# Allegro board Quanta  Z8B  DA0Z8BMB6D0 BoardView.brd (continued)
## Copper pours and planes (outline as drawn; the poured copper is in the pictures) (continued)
24737_DL on BOTTOM (solid shape): 160.58,189.63 160.58,187.98 160.51,187.9 159.77,187.9 159.77,189.63 159.9,189.76 160.46,189.76
51216_DRVH on BOTTOM (solid shape): 52.4,44.49 52.4,43.22 52.33,43.15 51.72,43.15 51.67,43.2 51.67,44.52 51.77,44.62 52.27,44.62
51216_DRVH on BOTTOM (solid shape): 55.99,34.74 55.99,34.51 55.88,34.41 55.58,34.41 55.48,34.51 54.94,34.51 54.76,34.33 54.76,31.95 54.74,31.92 54.59,31.92 54.56,31.95 54.56,34.74 54.94,35.12 55.6,35.12
51216_DRVL on BOTTOM (solid shape): 52.48,38.12 52.48,37.51 52.4,37.43 51.16,37.43 51,37.58 51,38.02 51.13,38.14 52.45,38.14
51216_DRVL on BOTTOM (solid shape): 53.55,32.71 53.55,31.9 53.54,31.9 52.61,31.9 52.27,32.23 52.27,32.68 52.33,32.73 53.52,32.73
51216_SW on BOTTOM (solid shape): 61.9,43.05 61.9,38.65 61.67,38.42 56.77,38.42 56.24,38.96 52.07,38.96 51.95,39.08 51.95,41.06 52.05,41.17 56.29,41.17 58.55,43.43 61.52,43.43
51216_SW on BOTTOM (solid shape): 56.39,35.48 56.39,35.2 56.24,35.04 55.88,35.04 55.58,35.35 54.79,35.35 54.36,34.92 54.36,31.95 54.33,31.92 54.18,31.92 54.15,31.95 54.15,35.4 54.41,35.65 56.21,35.65
51216_VBST on BOTTOM (solid shape): 56.04,34.11 56.04,33.34 55.91,33.22 55.4,33.22 55.17,32.99 55.17,31.95 55.15,31.92 54.99,31.92 54.97,31.94 54.97,33.75 55.37,34.16 55.99,34.16
51225_DH1 on TOP (solid shape): 43.59,61.92 43.59,61.66 43.41,61.49 42.47,61.49 42.45,61.46 42.45,61 42.42,60.98 42.27,60.98 42.22,61.03 42.22,61.79 42.39,61.97 43.03,61.97 43.16,62.1 43.41,62.1
51225_DH1 on BOTTOM (solid shape): 49.73,71.49 49.73,70.43 49.63,70.33 48.95,70.33 48.93,70.34 48.93,71.51 49.02,71.6 49.63,71.6
51225_DH2 on TOP (solid shape): 42.45,58.74 42.45,58.21 42.5,58.16 43.05,58.16 43.13,58.24 43.38,58.24 43.56,58.06 43.56,57.8 43.38,57.63 42.47,57.63 42.22,57.88 42.22,58.74 42.24,58.77 42.42,58.77
51225_DH2 on BOTTOM (solid shape): 48.82,47.01 48.82,45.87 48.77,45.81 48.01,45.81 47.93,45.89 47.93,47.06 47.96,47.08 48.74,47.08
51225_DL1 on TOP (solid shape): 44.38,60.98 44.38,60.72 44.2,60.55 42.67,60.55 42.65,60.57 42.65,60.75 42.67,60.78 43.72,60.78 43.77,60.83 43.77,60.98 43.94,61.16 44.2,61.16
51225_DL1 on BOTTOM (solid shape): 47.14,66.74 47.14,65.93 47.07,65.86 46.15,65.86 45.87,66.13 45.87,66.72 45.95,66.79 47.09,66.79
51225_DL2 on TOP (solid shape): 44.38,59 44.38,58.74 44.2,58.57 43.94,58.57 43.78,58.73 43.78,58.88 43.72,58.95 42.65,58.95 42.62,58.97 42.62,59.15 42.65,59.17 44.2,59.17
51225_DL2 on BOTTOM (solid shape): 49.97,54.2 49.97,53.71 49.81,53.56 47.68,53.56 47.65,53.59 47.65,54.4 47.73,54.48 49.69,54.48
51225_SW1 on TOP (solid shape): 42.55,63.98 42.55,63.72 42.37,63.54 41.84,63.54 41.63,63.34 41.63,61 41.61,60.98 41.45,60.98 41.43,61 41.43,63.47 42.11,64.15 42.37,64.15
51225_SW1 on BOTTOM (solid shape): 54.79,74.01 54.79,68.4 54.66,68.27 50.96,68.27 49.86,67.18 46.28,67.18 46.1,67.36 46.1,69.44 46.31,69.64 49.64,69.64 50.07,70.07 50.07,71.57 49.89,71.75 49,71.75 48.95,71.8 48.95,72.23 48.95,74.59 49.05,74.69 54.1,74.69
51225_SW2 on TOP (solid shape): 41.63,58.74 41.63,56.18 41.81,56 41.99,56 42.14,56.15 42.39,56.15 42.57,55.97 42.57,55.72 42.39,55.54 41.73,55.54 41.43,55.85 41.43,58.74 41.45,58.77 41.61,58.77
51225_SW2 on BOTTOM (solid shape): 53.14,52.57 53.14,46.88 52.99,46.73 50.4,46.73 49.86,47.26 48.01,47.26 47.93,47.34 47.93,49.98 47.58,50.34 45.65,50.34 45.09,50.89 45.09,52.8 45.26,52.98 52.73,52.98
51631_V5A on TOP (solid shape): 45.17,96.44 45.17,95.62 45.05,95.5 43.81,95.5 43.7,95.6 43.7,96.29 43.98,96.56 44.73,96.56 45.05,96.56
51631_V5A on BOTTOM (solid shape): 45.5,97.38 45.5,96.16 44.68,95.34 44.68,94.3 44.67,94.27 44.63,94.25 44.53,94.25 44.5,94.28 44.5,94.33 44.51,94.33 44.51,95.03 44.5,95.03 44.5,95.67 44.58,95.75 44.58,97.27 44.84,97.53 45.34,97.53
+AZA_VDD on TOP (solid shape): 33.29,25.92 33.29,25.17 33.68,24.79 33.68,23.94 33.66,23.92 33.64,23.92 33.12,23.92 32.71,24.33 32.71,24.55 32.5,24.76 32.5,25.07 32.1,25.48 32.1,26.42 32.13,26.46 32.76,26.46
+DDR_VTT_RUN on TOP (solid shape): 138.67,61.6 138.7,61.58 138.72,61.55 138.72,59.51 138.82,59.41 138.82,56.71 138.81,56.68 138.79,56.67 138.2,56 138.45,55.15 138.46,55.13 138.46,55.11 138.46,53.93 139.02,53.37 139.02,52.35 139.02,52.34 139.01,52.23 139.02,52.13 139.02,52.12 139.02,52 138.85,51.82 138.85,51.39 138.84,51.39 138.84,50.59 138.85,50.25 138.84,48.72 138.59,48.46 138.59,46.28 138.67,46.2 138.67,44.04 138.03,43.41 138.03,42.25 139.05,41.23 139.05,38.14 139.05,37.32 138.84,37.11 137.8,37.11 137.62,37.29 137.62,40.18 137.24,40.56 136.96,40.84 136.96,44.16 137.24,44.45 137.24,60.81 138.03,61.6
+DDR_VTT_RUN on BOTTOM (solid shape): 138.87,39.7 138.87,37.92 138.74,37.8 137.17,37.8 137.17,39.8 138.77,39.8
+DDR_VTT_RUN on BOTTOM (solid shape): 138.3,47.72 138.3,46.1 137.59,45.39 137.39,45.39 136.86,45.92 136.86,48.08 136.88,48.1 137.92,48.1
+DDR_VTT_RUN on BOTTOM (solid shape): 54.33,28.72 54.71,28.34 54.71,28.01 54.97,27.75 55.33,27.75 55.58,28.01 55.58,28.37 55.33,28.62 55.25,28.62 54.97,28.9 54.97,29.71 55.88,29.71 56.06,29.53 56.06,28.47 57.08,27.45 57.08,27.44 58.47,26.04 58.47,24.87 57.74,24.14 55.86,24.14 54.74,25.26 54.74,27.7 54.15,28.29 54.15,29.66 54.17,29.7 54.21,29.71 54.33,29.71
+DDR_VTT_RUN on BOTTOM (solid shape): 137.91,60.91 137.93,60.91 137.95,60.9 138.18,60.66 138.18,57.49 138.44,57.23 138.44,56.44 138.18,55.8 138.44,55.16 138.44,50.75 138.36,50.67 137.22,50.67 137.18,50.69 137.17,50.73 137.17,58.83 137.09,58.9 136.94,58.9 136.9,58.92 136.89,58.95 136.89,60.86 136.9,60.9 136.94,60.91
+DDR_VTT_RUN on IN1 (solid shape): 60.98,25.2 60.98,24.23 60.32,23.57 56.69,23.57 56.01,24.26 56.01,24.88 56.88,25.75 60.43,25.75
+DDR_VTT_RUN on IN1 (solid shape): 138.67,39.31 138.67,38.17 134.73,34.23 133.6,34.23 133,34.83 133,35.45 134.18,36.62 135.65,36.62 135.65,36.57 135.66,36.51 135.68,36.46 135.7,36.41 135.73,36.36 135.77,36.32 135.81,36.28 135.86,36.25 135.91,36.22 135.96,36.21 136.02,36.2 136.07,36.2 136.13,36.21 136.18,36.22 136.24,36.25 136.28,36.28 136.33,36.32 136.36,36.36 136.39,36.41 136.42,36.46 136.43,36.51 136.44,36.57 136.44,36.62 136.43,36.68 136.42,36.73 136.39,36.78 136.36,36.83 136.33,36.87 136.28,36.91 136.24,36.94 136.18,36.96 136.13,36.98 136.07,36.99 136.02,36.99 135.96,36.98 135.91,36.96 135.86,36.94 135.81,36.91 135.77,36.87 135.73,36.83 135.7,36.78 135.68,36.73 135.66,36.68 135.65,36.62 134.18,36.62 137.19,39.63 138.35,39.63
+FB_PLLAVDD on TOP (solid shape): 135.23,144.26 135.23,138.65 135.08,138.5 134.03,138.5 133.54,138.99 133.54,139.21 133.94,139.6 133.94,140.1 133.78,140.25 133.78,143.35 134.85,144.42 135.08,144.42
+FB_PLLAVDD on IN2 (solid shape): outline of 2246 points within 133.53,138.59 145.67,165.09
+G_SEN_PW on TOP (solid shape): 114.84,16.14 114.84,15.62 114.76,15.54 113.41,15.54 113.31,15.64 113.31,16.27 113.36,16.33 114.65,16.33
+G_SEN_PW on TOP (solid shape): 109.45,15.2 109.45,14.9 108.94,14.39 108.93,14.39 108.85,14.31 108.56,14.31 108.41,14.47 108.41,14.98 108.73,15.3 109.35,15.3
+G_SEN_PW on TOP (solid shape): 118.06,10.51 118.06,10.31 118.06,9.97 117.6,9.52 117.6,7.46 116.72,6.58 112.71,6.58 112.52,6.76 112.52,8.55 112.68,8.71 113.21,8.71 113.31,8.6 113.31,7.66 113.59,7.39 113.59,7.38 114.05,7.12 114.53,7.34 114.54,7.35 114.57,7.36 114.98,7.36 115,7.35 115.02,7.34 115.47,7.12 115.92,7.34 115.94,7.35 115.96,7.36 116.16,7.36 116.54,7.74 116.54,8.88 116.49,8.93 115.76,8.93 115.5,9.01 115.23,8.96 115.2,8.96 115.18,8.97 115.09,9.06 115.09,9.67 115.14,9.72 116.56,9.72 117.48,10.64 117.93,10.64
+G_SEN_PW on IN1 (solid shape): 118.93,14.86 118.93,11.52 117.98,10.57 117.98,10.26 117.76,10.04 117.54,10.04 117.4,10.18 117.4,10.96 118.3,11.87 118.3,14.51 117.24,15.57 109.88,15.57 108.95,14.64 108.95,14.39 108.79,14.23 108.53,14.23 108.37,14.39 108.37,15.17 109.36,16.17 109.36,16.18 117.6,16.18 117.6,16.18
+SM_VREF on TOP (solid shape): 94.81,76.76 94.81,76.02 94.81,75.98 95.03,75.76 95.68,75.76 95.94,75.51 95.94,74.01 95.55,73.62 95.55,73.01 95.54,72.95 95.53,72.89 95.53,72.84 95.53,70.92 95.55,70.91 95.55,67.29 94.26,66.01 93.58,66.01 93.25,66.34 93.25,70.96 93.5,71.21 93.5,74.42 93.5,74.82 93.88,75.2 93.88,76.68 94.14,76.93 94.64,76.93
+SM_VREF on TOP (solid shape): outline of 247 points within 97.61,80.39 99.7,84.78
+SMDDR_VREF_DIMM on TOP (solid shape): 95.01,38.33 95.01,36.36 95.02,36.35 95.02,34.76 94.8,34.54 93.5,34.54 93.32,34.71 93.32,36.35 92.95,36.73 92.95,38.71 93.07,38.83 94.52,38.83
+SMDDR_VREF_DIMM on TOP (solid shape): 114.6,52.7 114.6,50.72 114.6,50.71 114.6,49.25 114.52,49.17 114.49,49.16 114.46,49.16 114.31,49.18 114.15,49.13 114.12,49.12 114.09,49.14 113.96,49.27 113.96,50.38 113.64,50.71 113.64,52.57 113.84,52.78 114.51,52.78
+SMDDR_VREF_DIMM on TOP (solid shape): 113.43,40.53 113.57,40.51 113.71,40.53 114.46,40.53 115.24,39.74 115.24,38.8 115.2,38.76 115.16,38.75 115.14,38.76 114.74,38.87 114.36,38.7 112.75,38.7 112.73,38.73 112.73,39.97 113.29,40.53
+SMDDR_VREF_DIMM on BOTTOM (solid shape): 114.36,40.33 114.36,40.07 114.1,39.82 114.1,37.92 113.8,37.92 113.8,39.95 113.75,40.01 113.75,40.35 113.9,40.51 114.18,40.51
+SMDDR_VREF_DIMM on BOTTOM (solid shape): 114.13,50.69 114.58,50.23 114.58,49.44 114.55,49.36 114.46,49.34 114.3,49.36 114.14,49.32 114.13,49.32 114.1,49.32 113.85,49.57 113.85,50.31 113.77,50.39 113.77,50.59 113.77,50.6 113.77,52.65 113.8,52.67 114.13,52.67
+SMDDR_VREF_DIMM on IN2 (solid shape): outline of 3040 points within 92.38,36.29 119.34,50.67
+SMDDR_VREF_DQ0 on TOP (solid shape): outline of 103 points within 71.91,45.46 77.23,52.7
+SMDDR_VREF_DQ0 on BOTTOM (solid shape): 74.22,45.69 74.04,45.51 72.34,45.51 71.94,45.92 71.94,47.49 72.45,48 74.22,48
+SMDDR_VREF_DQ1 on TOP (solid shape): 77.09,64.75 77.09,59.43 75.87,58.21 73.56,58.21 73.44,58.34 73.44,58.92 73.77,59.25 75.33,59.25 75.81,59.73 75.81,61.04 75.68,61.18 75.68,63.74 75.44,63.98 74.83,63.98 74.73,64.08 74.73,64.84 74.84,64.95 76.89,64.95
+SMDDR_VREF_DQ1 on BOTTOM (solid shape): 74.22,58.35 74.11,58.23 73.53,58.23 73.5,58.25 73.48,58.29 73.48,60.75 73.65,60.91 74.22,60.91
+TPVDD on BOTTOM (solid shape): 168.23,18.31 168.23,14.47 168.22,14.47 168.22,14.02 167.97,13.77 167.09,13.77 166.81,14.05 166.81,16.33 165.53,17.61 161.29,17.61 160.94,17.96 160.94,19.17 161.35,19.58 166.97,19.58
+VGPU_CORE on TOP (solid shape): 191.69,168.23 191.69,162.17 191.44,161.92 173.69,161.92 173.69,161.92 173.33,161.92 172.98,162.27 172.98,167.94 172.97,167.94 172.97,169.34 173.22,169.59 181.74,169.59 182.86,170.71 189.21,170.71
+VGPU_CORE on TOP (solid shape): outline of 344 points within 141.87,153.63 152.79,163.1
+VGPU_CORE on BOTTOM (solid shape): 146.9,162.45 146.9,162.24 142.71,158.06 142.6,158.06 142.42,158.23 142.42,158.36 146.62,162.56 146.79,162.56
+VGPU_CORE on BOTTOM (solid shape): 148.92,162.43 148.92,162.26 142.74,156.08 142.61,156.08 142.46,156.24 142.46,156.38 148.6,162.53 148.82,162.53
+VGPU_CORE on BOTTOM (solid shape): 144.91,162.46 144.91,162.21 142.73,160.04 142.62,160.04 142.47,160.19 142.47,160.19 142.41,160.26 142.41,160.37 144.61,162.57 144.8,162.57
+VGPU_CORE on BOTTOM (solid shape): 151.63,160.51 151.63,160.21 151.49,160.07 150.71,160.07 144.34,153.7 144.08,153.7 144,153.78 144,153.95 150.61,160.57 151.58,160.57
+VGPU_CORE on BOTTOM (solid shape): 151.65,156.54 151.65,156.17 151.57,156.09 150.78,156.09 148.85,154.17 148.85,153.58 148.74,153.46 148.41,153.46 148.34,153.54 148.34,154.33 150.61,156.6 151.58,156.6
+VGPU_CORE on BOTTOM (solid shape): 151.67,158.44 151.67,158.08 151.54,157.94 150.6,157.94 146.79,154.13 146.79,153.79 146.59,153.59 146.26,153.59 146.02,153.83 146.02,153.96 150.62,158.56 151.55,158.56
+VGPU_CORE on BOTTOM (solid shape): 150.9,162.43 150.9,162.25 142.75,154.09 142.62,154.09 142.42,154.29 142.42,154.49 143.5,155.57 143.58,155.63 143.64,155.71 150.49,162.56 150.77,162.56
+VGPU_CORE on BOTTOM (solid shape): 172.28,170.73 174.96,170.73 175.16,170.53 175.18,170.42 175.09,170.35 174.86,169.67 175.46,170.07 175.48,170.16 175.56,170.2 178.92,170.2 179.29,170.57 179.39,170.59 179.46,170.52 179.87,170.24 180.21,170.61 180.24,170.68 180.31,170.71 189.11,170.71 191.67,168.14 191.67,166.64 191.71,166.6 191.71,163.07 190.58,161.94 173.66,161.94 172.98,162.63 172.98,168.04 173,168.06 172.72,168.34 171.21,168.34 171.01,168.54 171.01,171.04 171.1,171.14 171.87,171.14
+VGPU_CORE on SVCC (solid shape): 153.72,173.93 154.11,173.59 154.5,173.93 182.65,173.93 183.01,173.7 183.37,173.93 186,173.93 191.67,168.26 191.67,162.84 188.03,159.2 172.12,159.2 171.92,159.16 171.75,159.05 169.97,157.27 169.86,157.11 169.83,156.91 169.83,153.06 169.36,152.6 164.41,152.6 164.16,152.69 163.91,152.6 149.74,152.6 149.47,152.7 149.2,152.6 145.27,152.6 144.79,153.08 144.68,153.36 144.4,153.47 142.52,155.35 142.52,156.49 142.74,156.84 142.52,157.19 142.52,162.16 143.62,163.26 144.67,163.26 145.06,162.87 145.46,163.26 146.7,163.26 146.92,163.2 147.13,163.26 148.48,163.26 148.68,163.3 148.85,163.41 148.99,163.56 149.28,163.67 149.39,163.96 149.55,164.12 149.75,164.22 149.86,164.42 150.47,165.03 150.75,165.23 150.78,165.57 150.78,166.9 150.8,167.04 150.78,167.19 150.78,173.47 151.24,173.93
+VGPU_CORE on IN2 (solid shape): outline of 693 points within 146.08,153.49 156.09,160.5
+VREFDQ_SA_CPU on TOP (solid shape): outline of 649 points within 123.84,96.92 132.23,99.77
+VREFDQ_SB_CPU on TOP (solid shape): outline of 883 points within 123.84,93.64 131.4,96.97
+WL_VDD on TOP (solid shape): 191.37,59.25 191.39,59.21 191.39,55.3 191.38,55.27 191.36,55.27 191.12,54.98 191.23,54.63 191.27,54.56 191.24,54.48 191.14,54.15 191.36,53.87 191.39,53.85 191.39,53.83 191.39,53.62 190.97,53.2 190.97,51.98 191.39,51.55 191.39,48.52 190.71,47.83 189.77,47.83 189.72,47.83 189.62,47.82 189.45,47.75 189.39,47.59 189.38,47.44 189.35,47.41 188.7,47.41 186.74,45.45 184.48,45.45 183.95,45.98 183.95,47.16 184.26,47.47 186.98,47.47 187.74,48.23 187.81,48.29 187.86,48.35 188.32,48.81 190.09,48.81 190.17,48.9 190.17,54.1 190.44,54.37 190.44,56.97 190.17,57.23 190.17,58.13 188.32,59.99 188.32,60.83 188.52,61.03 189.59,61.03
+WL_VDD on BOTTOM (solid shape): 176.66,62.3 176.66,62.14 176.51,61.99 176.51,60.62 176.15,60.27 176.15,58.28 176,58.13 175.76,58.13 175.65,58.24 175.65,60.73 175.53,60.85 175.5,60.89 175.47,60.93 175.46,60.95 175.46,62.43 175.64,62.6 176.35,62.6
+WL_VDD on BOTTOM (solid shape): 188.58,48.98 188.58,47.14 188.43,46.99 187.89,46.99 187.84,46.95 186.22,46.95 186.2,46.93 185.86,46.93 185.86,46.93 184.57,46.93 184.55,46.91 184.55,46.83 184.41,46.69 184.41,46.19 184.77,45.83 184.77,45.39 184.62,45.24 183.56,45.24 183.42,45.38 183.42,45.69 183.22,45.88 183.22,46.84 183.35,46.97 183.86,46.97 184.08,47.19 185.08,47.19 185.08,47.19 187.89,47.19 187.89,47.19 187.99,47.29 187.99,47.41 187.99,47.43 188.03,47.46 188.03,47.99 187.99,48.03 187.99,49.04 188.14,49.19 188.37,49.19
+WL_VDD on BOTTOM (solid shape): 188.18,62.51 188.58,62.51 188.65,62.48 188.68,62.4 188.79,62.11 189.08,61.99 189.15,61.97 189.18,61.89 189.18,58.29 189.1,58.21 187.65,58.21 187.56,58.31 187.56,62.32 187.56,62.32 187.56,62.67 187.7,62.82 187.87,62.82
+WL_VDD on BOTTOM (solid shape): 170.18,51.64 170.22,51.63 170.23,51.59 170.23,49.79 170.19,49.66 170.19,49.51 170.19,46.53 170.58,46.14 170.58,45.85 170.44,45.71 169.28,45.71 169.18,45.81 169.18,47.32 169.1,47.4 169.1,47.42 169.06,47.57 168.96,47.7 168.96,49.22 169.34,49.64 168.87,49.97 168.86,49.97 168.84,49.97 168.78,50.02 168.78,51.59 168.8,51.63 168.84,51.64
+WL_VDD on BOTTOM (solid shape): 165.43,62.66 166.93,62.66 167.05,62.53 167.05,62.12 166.85,61.92 166.02,61.92 166.01,61.91 165.73,61.91 165.12,61.3 165.12,60.48 164.97,60.33 164.97,58.27 164.96,58.23 164.92,58.21 163.76,58.21 163.71,58.27 163.71,60.94 163.76,61.03 163.87,61.02 164.49,61.32 163.87,61.61 163.76,61.6 163.71,61.69 163.71,62.81 163.91,63.01 165.08,63.01
+WL_VDD on IN1 (solid shape): 171.45,46.1 171.45,45.33 171.38,45.26 169.7,45.26 169.39,45.56 169.39,45.99 169.66,46.26 171.29,46.26
+WL_VDD on IN1 (solid shape): 184.84,45.79 184.84,45.57 184.5,45.23 181.07,45.23 180.81,45.48 180.81,46.38 180.96,46.53 182.39,46.53 182.39,46.47 182.4,46.42 182.42,46.36 182.44,46.31 182.47,46.26 182.51,46.22 182.55,46.18 182.6,46.15 182.65,46.13 182.7,46.11 182.76,46.11 182.82,46.11 182.87,46.11 182.93,46.13 182.98,46.15 183.02,46.18 183.07,46.22 183.1,46.26 183.13,46.31 183.16,46.36 183.17,46.42 183.18,46.47 183.18,46.53 183.17,46.58 183.16,46.64 183.13,46.69 183.1,46.74 183.07,46.78 183.02,46.82 182.98,46.85 182.93,46.87 182.87,46.89 182.82,46.89 182.76,46.89 182.7,46.89 182.65,46.87 182.6,46.85 182.55,46.82 182.51,46.78 182.47,46.74 182.44,46.69 182.42,46.64 182.4,46.58 182.39,46.53 180.96,46.53 181.7,47.26 183.37,47.26
+WL_VDD on IN2 (solid shape): outline of 177 points within 162.93,45.08 170.56,63.11
+WL_VDD on IN2 (solid shape): outline of 616 points within 175.63,45.43 185.14,63.2
ADOGND on TOP (solid shape): 8.81,15.41 8.81,13.65 8.74,13.58 8.74,12.54 8.56,12.36 7.75,12.36 7.6,12.52 7.6,13.32 7.27,13.65 5.74,13.65 5.34,14.06 5.34,15.5 5.52,15.68 8.54,15.68
ADOGND on TOP (solid shape): 30.48,22.64 30.48,21.91 30.1,21.53 25.68,21.53 25.23,21.99 25.23,22.29 25.41,22.47 25.48,22.47 25.72,22.52 25.92,22.66 25.99,22.72 26.68,22.72 26.87,22.75 27.05,22.84 30.27,22.84
ADOGND on TOP (solid shape): 15.25,24.56 15.43,23.15 14.95,21.82 14.95,18.36 15.27,15.68 13.34,13.8 12.6,13.06 12.6,12.69 12.3,12.39 11.54,12.39 11.38,12.54 11.38,13.11 12.82,14.55 12.82,15.77 13.41,16.64 12.91,17.56 12.91,22.62 13.38,23.75 12.41,24.5 10.68,24.5 10.62,24.55 10.62,25.04 10.8,25.22 14.6,25.22
ADOGND on BOTTOM (solid shape): 13.52,26.32 15.3,24.41 14.95,21.82 14.95,18.36 15.08,15.25 12.41,13.65 2.54,13.65 2.54,13.34 2.76,12.7 2.86,12.03 2.93,11.27 3.05,10.51 3.05,10.09 2.9,9.94 1.1,9.94 0.92,10.93 0.83,11.93 0.74,12.39 0.51,12.8 0.51,15.63 0.52,15.67 0.56,15.68 1.76,15.68 1.83,15.61 1.83,14.67 2.37,14.14 4.91,14.14 5.34,14.57 5.34,15.26 5.76,15.68 9.73,15.68 9.78,15.63 9.78,14.93 10.62,14.09 12.4,14.09 13.21,14.9 13.21,16.09 13.4,16.88 12.94,17.55 12.92,17.56 12.91,17.59 12.91,22.59 12.92,22.62 12.94,22.63 13.4,23.66 12.62,24.48 12.59,24.48 12.57,24.5 10.67,24.5 10.59,24.58 10.59,25.54 11.37,26.32
ADOGND on SVCC (solid shape): outline of 99 points within 2.03,9.21 39.65,32.45
ADOGND on IN1 (solid shape): 15.43,23.81 15.44,23.67 15.44,23.52 15.44,23.46 15.31,22.6 14.95,21.82 14.95,18.36 15.31,17.58 15.44,16.73 15.44,16.65 14.54,14.53 12.41,13.65 2.54,13.65 2.54,13.34 2.76,12.7 2.86,12.03 2.95,11.09 3.13,10.17 3.02,10.06 1.07,10.06 0.91,10.99 0.83,11.93 0.74,12.39 0.51,12.8 0.51,15.63 0.52,15.67 0.56,15.68 1.71,15.68 1.81,15.58 1.81,14.62 2.34,14.09 4.86,14.09 5.39,14.62 5.39,15.23 5.84,15.68 6.25,15.68 6.29,15.68 6.31,15.66 8.5,15.66 8.53,15.68 8.56,15.68 9.72,15.68 9.78,15.61 9.78,14.9 10.55,14.14 12.42,14.14 13.21,14.92 13.21,16.08 13.4,16.87 12.94,17.55 12.92,17.56 12.91,17.59 12.91,22.59 12.92,22.62 12.94,22.63 13.4,23.32 13.19,24.13 13.78,24.72 14.52,24.72
ADOGND on IN2 (solid shape): 14.88,25.25 15.44,23.55 14.95,21.82 14.95,18.36 15.31,17.58 15.44,16.73 15.44,16.65 14.54,14.53 12.41,13.65 2.54,13.65 2.54,13.34 2.76,12.7 2.86,12.03 3.08,10.37 3.59,8.78 1.42,8.78 1.02,10.34 0.83,11.93 0.74,12.39 0.51,12.8 0.51,15.63 0.52,15.67 0.56,15.68 1.76,15.68 1.81,15.63 1.81,14.62 2.34,14.09 4.86,14.09 5.36,14.6 5.36,15.25 5.8,15.68 9.73,15.68 9.78,15.63 9.78,14.93 10.62,14.09 12.4,14.09 13.21,14.9 13.21,16.09 13.4,16.88 12.94,17.55 12.92,17.56 12.91,17.59 12.91,22.59 12.92,22.62 12.94,22.63 13.4,23.66 12.63,24.47 10.86,24.47 10.65,24.68 10.65,25.12 10.75,25.22 12.97,25.22 13,25.25
ADOGND on SGND (solid shape): outline of 98 points within 0.51,9.21 39.65,32.45
BAT-V on TOP (solid shape): 179.1,189.48 179.1,182.31 178.79,182.01 173.94,182.01 173.64,182.31 173.64,187.44 173.99,187.8 174.73,187.8 175.42,188.49 175.42,189.4 175.65,189.63 178.95,189.63
BAT-V on BOTTOM (solid shape): 179.1,190.47 179.1,182.44 178.79,182.14 177.37,182.14 177.23,182.28 177.23,182.94 176.69,183.48 176.34,183.48 176.27,183.56 176.27,190.78 176.41,190.92 178.64,190.92
CCD_PWR on TOP (solid shape): 112.24,175.28 112.24,174.74 111.74,174.24 111.74,172.51 111.48,172.26 110.65,172.26 110.49,172.41 110.49,175.02 110.95,175.48 112.04,175.48
CCD_PWR on BOTTOM (solid shape): 112.35,175.1 112.35,174.59 112.22,174.47 110.47,174.47 110.47,174.69 111.64,174.69 111.64,174.97 110.47,174.97 110.47,175.2 112.25,175.2
CON_BAT-V on TOP (solid shape): 179.35,194.15 179.35,190.65 178.95,190.24 175.39,190.24 175.19,190.04 175.19,189.68 174.96,189.45 173.89,189.45 173.79,189.55 173.79,190.32 173.99,190.52 173.99,191.36 175.53,192.89 175.53,194.04 176.13,194.63 178.87,194.63
CON_BAT-V on BOTTOM (solid shape): 179.43,194.43 179.43,193.44 178.85,192.86 176.05,192.86 175.7,193.21 175.7,194.4 176.2,194.91 178.95,194.91
CON_BAT-V on IN1 (solid shape): 179.28,194.48 179.28,193.49 178.79,193.01 175.75,193.01 175.57,193.19 175.57,194.38 176.1,194.91 178.85,194.91
CON_BAT-V on IN2 (solid shape): 179.23,194.4 179.23,193.26 178.82,192.86 175.95,192.86 175.59,193.21 175.59,194.33 176.1,194.84 178.79,194.84
CRTVDD5 on TOP (solid shape): outline of 439 points within 7.88,102.05 17.3,108.4
CS_SW1 on BOTTOM (solid shape): 61.27,84.86 61.27,83.51 61.26,83.5 61.27,83.49 61.27,82.85 59.78,82.85 59.78,82.29 61.27,82.29 61.27,80.56 61.09,80.38 58.55,80.38 57.97,79.8 55.91,79.8 55.66,80.05 55.66,81.45 55.35,81.76 55.35,83.86 55.4,83.91 55.45,83.91 55.45,83.91 56.1,83.91 56.1,83.91 57.23,83.91 57.24,83.93 58.06,83.93 58.58,84.45 58.58,84.83 58.83,85.08 61.04,85.08
CS_SW2 on BOTTOM (solid shape): 63.83,94.31 63.83,92.78 63.76,92.7 62.4,92.7 62.4,92.14 63.76,92.14 63.83,92.07 63.83,89.93 62.74,88.84 59.89,88.84 58.12,90.62 58.12,92.65 58.21,92.75 58.9,92.75 58.9,92.75 59.26,92.75 59.39,92.63 60.3,92.63 60.68,93.01 60.68,94.2 61.11,94.63 63.5,94.63
DDR_VTTREF on BOTTOM (solid shape): 53.55,29.71 53.55,28.9 53.34,28.69 52.35,28.69 52.12,28.92 52.12,29.13 52.38,29.38 53.21,29.38 53.34,29.51 53.34,29.69 53.37,29.71 53.54,29.71
ECAGND on TOP (solid shape): 186.85,49.85 186.85,49.47 186.72,49.35 185.2,49.35 184.99,49.55 184.99,50.31 185.04,50.36 186.34,50.36
ECAGND on TOP (solid shape): 187.25,53.34 187.25,53 187.13,52.87 187.11,52.86 187.08,52.86 186.91,52.88 186.75,52.83 184.93,52.83 184.68,53.08 184.68,53.37 185.01,53.7 186.9,53.7
ECAGND on IN1 (solid shape): 187.13,53.4 187.13,52.99 187.09,52.91 187.01,52.89 186.55,52.46 187.09,52.14 187.19,52.13 187.23,52.05 187.23,50.02 187.22,49.99 187.19,49.97 186.92,49.79 186.88,49.47 186.88,49.44 186.87,49.42 186.78,49.32 186.44,49.32 186.21,49.55 186.21,51.86 186.16,51.91 186.16,53.17 186.51,53.51 187.02,53.51
HDMI_5V on TOP (solid shape): 17.58,63.04 17.58,61.64 17.2,61.26 16.64,61.26 16.1,60.72 16.1,60.63 16.09,60.62 16.09,60.25 15.85,60.01 15.14,60.01 14.33,59.2 10.9,59.2 10.67,59.43 10.67,60.5 11.02,60.86 13.09,60.86 13.77,61.54 14.38,61.54 14.38,61.48 14.39,61.43 14.41,61.38 14.44,61.33 14.47,61.29 14.51,61.25 14.55,61.22 14.6,61.19 14.65,61.17 14.7,61.16 14.76,61.16 14.81,61.16 14.84,61.16 15.39,61.16 15.42,61.17 15.47,61.17 15.57,61.18 15.61,61.19 15.65,61.2 15.69,61.23 15.72,61.26 15.75,61.3 15.76,61.34 15.77,61.38 15.78,61.52 15.78,61.57 15.77,61.71 15.76,61.75 15.75,61.79 15.72,61.83 15.69,61.86 15.65,61.89 15.61,61.9 15.57,61.91 15.47,61.92 15.42,61.93 15.39,61.93 14.61,61.93 14.47,61.79 14.44,61.74 14.41,61.7 14.39,61.65 14.38,61.59 14.38,61.54 13.77,61.54 15.42,63.19 17.43,63.19
L_SPK+ on TOP (solid shape): 101.59,12.36 103.92,12.36 104.14,12.13 104.14,10.23 103.99,10.08 100.72,10.08 100.56,10.23 100.56,12.34 100.72,12.49 101.46,12.49
L_SPK+ on TOP (solid shape): 35.63,29.37 35.92,29.37 36.02,29.27 36.02,28.97 35.92,28.87 34.93,28.87 34.7,28.64 33.69,28.64 33.61,28.73 32.59,28.73 32.59,28.92 33.62,28.92 33.63,28.94 34.28,28.94 34.72,29.38 35.61,29.38
L_SPK+ on BOTTOM (solid shape): 101.35,13.43 101.35,12.24 101.15,12.03 101.15,11.09 100.94,10.89 100.28,10.89 100,11.17 100,13.18 100.39,13.56 101.22,13.56
L_SPK+ on BOTTOM (solid shape): 35.68,29.24 37.24,29.24 37.4,29.08 37.84,29.08 37.85,29.07 37.96,29.05 38.07,29.05 38.09,29.05 38.11,29.04 38.28,28.87 38.28,28.03 38.08,27.83 37.34,27.83 37.11,28.06 35.65,28.06 35.22,28.49 34.67,28.49 34.37,28.78 34.37,29.17 34.52,29.32 35.6,29.32
L_SPK+_1 on TOP (solid shape): 104.25,9.49 104.25,8.11 104.25,8.1 104.25,7.57 105.07,6.75 105.07,6.27 104.84,6.04 104.03,6.04 103.05,7.02 103.05,9.21 103.51,9.67 104.07,9.67
L_SPK+_1 on BOTTOM (solid shape): 105.29,8.07 105.29,6.52 104.83,6.06 103.64,6.06 103.62,6.07 103.6,6.08 103.45,6.21 103.26,6.24 103.24,6.24 103.22,6.25 103.05,6.42 103.05,7.64 103.59,8.17 105.19,8.17
L_SPK- on TOP (solid shape): 105.62,12.24 105.62,10.25 105.49,10.13 104.58,10.13 104.54,10.14 104.53,10.18 104.53,12.29 104.65,12.41 105.44,12.41
L_SPK- on TOP (solid shape): 35.89,30.01 35.89,29.69 35.76,29.56 34.7,29.56 34.19,29.05 33.71,29.05 33.63,29.13 32.66,29.13 32.61,29.19 32.61,29.31 32.62,29.32 33.59,29.32 33.65,29.38 34.16,29.38 34.88,30.09 35.8,30.09
L_SPK- on BOTTOM (solid shape): 105.31,13 105.31,10.99 105.19,10.86 104.22,10.86 104.14,10.94 104.14,13.2 104.32,13.38 104.93,13.38
L_SPK- on BOTTOM (solid shape): 38.86,30.55 38.86,29.89 38.85,29.85 38.81,29.84 38.46,29.84 38.33,29.71 38.29,29.69 38.26,29.71 37.93,29.8 37.65,29.6 37.57,29.53 34.8,29.53 34.7,29.63 34.7,30.09 34.77,30.17 34.78,30.17 34.81,30.14 34.92,30.14 34.93,30.14 35.05,30.12 35.18,30.14 35.19,30.14 35.58,30.14 35.59,30.14 35.71,30.12 35.84,30.14 35.85,30.14 36.57,30.14 36.58,30.14 36.92,30.18 37.08,30.48 37.09,30.5 37.26,30.68 38.74,30.68
L_SPK-_1 on TOP (solid shape): 105.53,9.61 105.53,9.56 105.52,9.55 105.52,8.16 106.56,7.11 106.56,6.39 106.66,6.29 106.66,5.83 106.61,5.78 105.67,5.78 105.45,6 105.45,6.85 105.45,6.91 104.63,7.73 104.63,8.26 104.63,8.27 104.63,9.44 104.83,9.64 105.49,9.64
L_SPK-_1 on BOTTOM (solid shape): 106.53,8.1 106.53,6.38 106.54,6.37 106.54,6.29 106.61,6.22 106.61,5.62 106.22,5.23 106.22,4.81 106.1,4.69 105.69,4.69 105.36,5.02 105.36,6.04 105.77,6.44 105.77,8.1 105.87,8.2 106.43,8.2
LANCT3 on TOP (solid shape): 27.69,85.56 27.69,75.68 27.38,75.38 26.29,75.38 25.75,75.93 25.75,84.76 24.33,86.18 21.47,86.18 21.19,86.45 21.19,87.01 21.34,87.17 21.34,89.24 21.6,89.5 23.75,89.5
LANCT3 on BOTTOM (solid shape): 23.83,90.94 23.83,89.94 23.67,89.78 23.67,89.76 22.94,89.03 22.94,86.75 23.17,86.52 23.17,86.4 22.86,86.1 22.25,86.1 22.17,86.19 20.79,86.19 19.46,87.52 18.65,87.52 17.81,88.36 17.81,89.27 17.85,89.31 17.85,90.15 18.7,91 21.85,91 22.25,91.41 23.36,91.41
LANVCC on TOP (solid shape): 35.11,96.12 35.11,90.62 34.4,89.91 34.4,79.88 32.59,78.07 32.59,77.99 32.58,77.98 32.43,77.73 32.38,77.44 32.38,77.03 32.37,77 32.33,76.98 32.19,76.98 32.15,77 32.14,77.03 32.14,77.44 32.06,77.78 31.86,78.06 31.85,78.07 31.83,78.11 31.83,78.63 32.29,79.08 32.29,80.2 32.36,80.28 32.37,80.28 32.73,80.46 32.96,80.79 32.87,81.55 32.19,81.91 31.81,81.91 31.77,81.93 31.75,81.96 31.75,82.11 31.77,82.14 31.81,82.16 32.19,82.16 32.93,82.62 32.85,83.49 32.85,89.1 32.36,89.58 26.04,89.58 24.3,91.32 24.3,94.73 24.75,95.19 24.75,95.84 25.37,96.45 25.37,97.01 25.38,97.02 26.27,97.02 26.29,97 26.29,96.79 25.89,96.39 25.89,95.32 25.4,94.84 25.4,92.88 27.31,90.98 32.06,90.98 32.24,90.8 32.87,90.8 33.28,91.2 33.28,95.67 32.88,96.08 32.87,96.09 32.67,96.42 32.33,96.63 32.32,96.63 32.21,96.74 32.21,96.98 32.49,97.26 33.96,97.26
LANVCC on BOTTOM (solid shape): 25.84,95.59 25.84,95.41 25.63,95.2 24.15,95.2 23.88,95.47 23.88,96.13 24.06,96.31 25.12,96.31
LANVCC on BOTTOM (solid shape): outline of 205 points within 29.39,96.67 33.96,101.91
LCDVCC on TOP (solid shape): 107.43,175.81 107.43,174.07 107.79,173.71 108.37,173.71 108.4,173.68 108.4,172.11 107.38,171.09 107.38,170.6 106.66,169.88 106.32,169.88 105.94,169.5 105.94,169.02 105.7,168.78 104.3,168.78 104.22,168.85 104.22,169.92 104.4,170.11 105.27,170.11 106.04,170.88 106.04,173.63 105.61,174.07 104.17,174.07 104,174.24 104,176.26 104.12,176.38 106.86,176.38
LINE1L_R on TOP (solid shape): 26.35,27.72 27.41,27.72 27.41,27.53 26.38,27.53 26.3,27.45 26.22,27.45 25.96,27.2 25.38,27.2 25.38,27.67 25.49,27.78 26.3,27.78
LINE1R_R on TOP (solid shape): 26.26,28.3 26.26,28.25 26.38,28.13 27.39,28.13 27.41,28.11 27.41,27.93 26.37,27.93 26.34,27.91 25.58,27.91 25.5,27.98 25.5,28.36 25.6,28.47 26.1,28.47
MIC2-VREFO on IN1 (solid shape): 19.21,24.45 19.21,23.95 19.08,23.82 18.06,23.82 17.94,23.95 17.94,24.07 18.7,24.83 18.83,24.83
MOD_EN_5V on TOP (solid shape): 191.31,94.25 192.54,94.25 192.59,94.2 192.59,91.17 192.45,91.02 191.83,91.02 191.63,91.22 191.63,92.69 191.19,93.13 191.19,94.17 191.27,94.26 191.31,94.26
NV_PLLVDD on TOP (solid shape): 155.46,160.33 155.46,154.45 155.34,154.33 154.6,154.33 154.52,154.41 154.52,155.82 154.53,155.86 154.57,155.87 154.58,155.87 154.77,155.92 154.91,156.06 154.94,156.45 154.62,156.66 154.55,156.69 154.52,156.76 154.52,158.28 154.55,158.35 154.62,158.38 154.97,158.76 154.62,159.14 154.55,159.18 154.52,159.24 154.52,159.43 153.86,160.09 153.62,160.09 153.48,160.23 153.48,160.56 153.61,160.69 155.1,160.69
PEX_PLLVDD on TOP (solid shape): 138,144.24 138,142.49 138.15,142.34 138.15,140.76 137.77,140.38 137.77,140.07 137.7,140 137.39,140 137.32,140.07 137.32,144.16 137.49,144.34 137.9,144.34
R_SPK+ on TOP (solid shape): 108.11,12.05 108.11,11.5 108.37,11.23 108.37,10.2 108.36,10.17 108.32,10.15 107.45,10.15 107.32,10.28 107.32,12.08 107.48,12.25 107.9,12.25
R_SPK+ on TOP (solid shape): 35.71,31.31 35.71,31.03 35.59,30.9 34.93,30.9 33.95,29.93 32.6,29.93 32.59,29.94 32.59,30.11 32.6,30.12 33.75,30.12 34.56,30.94 34.56,31.27 34.7,31.41 35.61,31.41
R_SPK+ on BOTTOM (solid shape): 35.76,32.05 35.76,31.29 35.5,31.02 34.65,31.02 34.52,31.16 34.52,32.17 34.7,32.35 35.46,32.35
R_SPK+ on BOTTOM (solid shape): 108.39,13.15 108.39,11.14 108.26,11.02 107.29,11.02 107.27,11.04 107.27,13.28 107.24,13.31 107.23,13.33 107.23,13.36 107.4,13.53 108.01,13.53
R_SPK+_1 on TOP (solid shape): 109.49,8.26 109.49,6.72 109.76,6.46 109.76,5.45 109.4,5.1 108.87,5.1 108.79,5.17 108.8,5.18 108.8,6.12 108.43,6.5 108.43,7.6 107.37,8.65 107.37,9.52 107.47,9.62 108.13,9.62
R_SPK+_1 on BOTTOM (solid shape): 109.68,8.1 109.68,7.23 109.91,7 110.06,7 110.34,6.72 110.34,6.11 110.32,6.09 109.83,6.09 109.5,5.76 109.5,5.23 109.4,5.12 108.97,5.12 108.84,5.25 108.84,5.91 108.26,6.5 108.26,8.12 108.31,8.17 109.61,8.17
R_SPK- on TOP (solid shape): 106.89,12.18 106.89,10.23 106.87,10.19 106.84,10.18 106.02,10.18 106,10.2 106,12.21 106.25,12.46 106.61,12.46
R_SPK- on TOP (solid shape): 35.9,30.67 35.9,30.36 35.78,30.23 34.86,30.23 34.17,29.54 32.64,29.54 32.61,29.57 32.61,29.68 32.64,29.71 33.64,29.71 33.73,29.8 34,29.8 34.98,30.78 35.8,30.78
R_SPK- on BOTTOM (solid shape): 106.89,13.12 106.89,11.12 106.76,10.99 105.8,10.99 105.72,11.07 105.72,13.33 105.9,13.51 106.51,13.51
R_SPK- on BOTTOM (solid shape): 38.97,32.25 38.97,31.69 38.63,31.35 37.41,31.35 36.9,30.85 36.87,30.84 36.86,30.85 36.46,30.79 36.33,30.41 36.31,30.32 36.23,30.29 34.91,30.29 34.8,30.39 34.8,30.65 34.88,30.72 35.68,30.72 36.02,31.06 36.02,31.39 36.45,31.82 36.47,31.82 37.13,32.48 38.74,32.48
R_SPK-_1 on TOP (solid shape): 106.99,9.44 106.99,8.44 108.03,7.4 108.03,5.38 107.8,5.15 107.34,5.15 107.07,5.43 107.07,7.14 106.93,7.28 105.9,8.31 105.9,9.39 106.18,9.67 106.76,9.67
R_SPK-_1 on BOTTOM (solid shape): 107.78,8.07 107.78,6.42 108.41,5.78 108.41,5.71 108.41,5.71 108.41,5.45 108.39,5.43 107.95,5.43 107.73,5.2 107.42,5.2 107.01,5.61 107.01,8.1 107.14,8.22 107.42,8.22 107.62,8.22
REGOUT on TOP (solid shape): 26.85,102.56 26.85,102.2 26.62,101.97 26.62,100.94 26.62,100.94 26.62,100.05 26.54,99.98 25.9,99.98 25.58,100.3 25.58,100.65 24.94,101.29 24.94,102.43 25.13,102.62 26.79,102.62
REGOUT on BOTTOM (solid shape): 26.85,104.97 26.85,102.18 26.72,102.05 25.07,102.05 24.46,102.66 24.46,104.97 24.59,105.1 26.72,105.1
RING2 on TOP (solid shape): 7.65,11.91 7.65,10.45 7.48,10.28 6.58,10.28 6.44,10.43 6.44,11.89 6.56,12.01 7.54,12.01
RING2 on TOP (solid shape): 26.2,30.26 26.2,29.9 26.37,29.72 27.38,29.72 27.39,29.7 27.39,29.56 27.36,29.53 26.4,29.53 26.38,29.51 25.53,29.51 25.46,29.43 25.35,29.43 25.2,29.58 25.2,29.79 25.7,30.28 25.82,30.28 25.84,30.31 26.15,30.31
RING2 on IN2 (solid shape): 7.51,12.49 7.52,12.48 7.87,12.27 8.21,12.49 8.23,12.52 9.38,12.52 9.58,12.31 9.58,11.09 9.35,10.86 6.18,10.86 6.1,10.91 6.09,11.01 6.12,11.31 5.92,11.55 5.92,12.21 6.23,12.52 7.47,12.52
RING2 on IN2 (solid shape): outline of 376 points within 17.12,23.61 26.6,31.03
RING2_R on TOP (solid shape): 4.65,15.42 4.65,13.78 4.3,13.43 4.3,12.39 4.25,12.34 3.84,12.34 3.64,12.13 3.64,11.27 4.17,10.74 4.47,10.74 4.7,10.97 4.7,12.85 5.08,13.23 7.02,13.23 7.33,12.91 7.33,12.42 7.23,12.32 5.61,12.32 5.61,11.54 5.58,11.51 5.4,11.27 5.47,10.97 5.49,10.9 5.46,10.83 5.31,10.52 5.43,10.21 4.32,9.1 3.75,9.1 3.64,9.21 3.64,9.21 3.05,9.21 2.16,10.1 2.16,14.9 2.95,15.68 4.39,15.68
SENSEA on TOP (solid shape): 27.45,31.56 27.45,31.23 27.36,31.14 25.8,31.14 25.77,31.11 25.76,31.11 25.49,30.84 24.83,30.84 24.75,30.93 24.75,31.43 25.04,31.73 27.28,31.73
SLEEVE on TOP (solid shape): 20.02,26.14 20.02,25.42 19.87,25.27 19.08,25.27 18.82,25.52 18.82,26.19 18.83,26.19 18.92,26.23 19,26.31 19.02,26.32 19.04,26.32 19.83,26.32
SLEEVE on BOTTOM (solid shape): 20.71,26.21 20.71,24.38 20.96,24.12 20.96,23.67 20.63,23.34 19.38,23.34 19.05,23.67 19.05,26.26 19.33,26.54 20.38,26.54
SLEEVE on IN2 (solid shape): 21.36,24.3 21.46,24.25 21.57,24.23 21.59,24.22 21.99,23.83 21.99,23.09 21.63,22.73 20.14,22.73 19.91,22.96 19.91,23.92 20.28,24.3
SLEEVE on IN2 (solid shape): 27.33,29.23 27.33,26.51 27.24,26.42 27.22,26.41 27.01,26.39 26.85,26.3 26.83,26.29 26.81,26.28 26.37,26.28 26.19,26.46 26.19,28.06 26.19,28.07 26.15,28.41 25.86,28.59 25.84,28.59 25.66,28.78 25.66,29 25.72,29.06 25.75,29.18 25.8,29.26 25.88,29.31 25.94,29.32 26.54,29.32 26.7,29.34 26.85,29.41 27.15,29.41
SLEEVE_R on TOP (solid shape): 16.36,29.2 16.36,27.6 16.18,27.42 15.17,27.42 13.72,25.98 4.93,25.98 4.07,25.11 4.07,24.66 3.92,24.5 2.34,24.5 2.14,24.71 2.14,25.01 4.12,26.99 12.55,26.99 13.85,28.29 14.86,28.29 15.62,29.04 15.62,29.21 15.69,29.28 16.29,29.28
SLEEVE_R on TOP (solid shape): 18.52,27.27 18.52,26.85 18.51,26.82 18.5,26.81 18.37,26.53 18.5,26.26 18.51,26.24 18.52,26.22 18.52,25.62 18.33,25.43 16.25,25.43 15.8,25.88 15.8,26.34 15.89,26.42 17.35,26.42 17.73,26.8 17.73,27.31 17.82,27.4 18.39,27.4
SLEEVE_R on IN1 (solid shape): 16.71,28.82 16.71,25.66 16.27,25.66 15.54,26.4 15.54,26.55 15.43,27.25 14.93,26.75 14.93,26.63 14.56,26.63 14.18,26.85 13.79,27.03 13.73,27.1 13.74,27.18 13.93,27.51 14.09,27.86 14.37,28.14 15.2,28.14 16.06,29 16.53,29
SMDDR_VREF_DQ0_M1 on TOP (solid shape): 73.7,51.31 73.74,51.3 73.76,51.26 73.76,50.4 73.66,50.31 72.95,50.31 71.98,49.35 70.83,49.35 70.81,49.34 70.68,49.47 70.68,49.98 70.7,50.01 70.72,50.02 71.27,50.31 71.48,50.89 71.48,51.24 71.56,51.31
SMDDR_VREF_DQ1_M1 on TOP (solid shape): 74.35,64.67 74.35,63.92 74.67,63.59 75.19,63.59 75.21,63.57 75.21,62.76 75.08,62.63 74.17,62.63 73.97,62.83 72.14,62.83 71.61,63.37 71.61,64.46 72.01,64.86 72.39,64.86 74.15,64.86
SP_PLLVDD on TOP (solid shape): 154.18,159.33 154.18,158.47 154.38,158.28 154.38,157.99 154.18,157.8 154.18,156.3 154.18,156.25 154.18,156.2 154.18,154.45 154.06,154.32 153.43,154.32 153.28,154.47 153.28,157.73 152.88,158.13 152.88,159.63 152.98,159.72 153.79,159.72
SYSTEM_AGND on BOTTOM (solid shape): 38.13,62.05 38.13,58.82 37.93,58.62 37.93,57.85 37.75,57.68 36.81,57.68 36.43,58.06 36.43,61.74 36.89,62.2 37.98,62.2
TH_FAN_POWER on BOTTOM (solid shape): 60.25,101.49 62.41,101.49 62.74,101.82 63.35,101.82 63.39,101.81 63.4,101.77 63.4,101.14 63.17,100.91 62.51,100.91 62.44,100.98 60.46,100.98 60.38,100.91 59.47,100.91 58.96,101.42 58.96,101.75 59.24,102.02 59.72,102.02
TP_PWR on BOTTOM (solid shape): 113.59,176.8 113.59,176.12 113.42,175.94 113.07,175.94 113.07,175.94 112.86,175.94 112.37,175.46 110.47,175.46 110.47,175.71 111.64,175.71 111.64,175.96 110.47,175.96 110.47,176.19 111.71,176.19 112.24,176.72 112.25,176.72 112.36,176.79 112.44,176.88 112.46,176.9 112.48,176.9 113.49,176.9
USBPWR1 on TOP (solid shape): 21.87,46.17 22.33,46.17 22.89,45.61 22.89,44.54 22.71,44.37 21.67,44.37 21.44,44.14 21.44,41.57 19.8,39.93 19.51,39.93 19.5,39.97 19.18,40.27 18.79,40.07 17.39,40.07 16.73,39.41 16.41,39.41 16.17,39.66 15.69,39.66 15.55,39.51 15.48,39.48 15.41,39.5 15.11,39.59 14.84,39.41 14.23,39.41 14.08,39.26 13.69,39.26 13.06,39.9 13.06,40.63 13.37,40.94 15.32,40.94 16.06,41.67 16.06,43.22 15.24,44.04 15.24,44.6 15.65,45 16.36,45 17.15,44.21 19.51,44.21 20.53,45.23 20.53,45.56 21.14,46.17 21.87,46.17
USBPWR1 on BOTTOM (solid shape): 22.3,45.71 22.3,43.3 21.86,42.86 18.69,42.86 18.42,42.59 18.42,40.56 18.11,40.25 17.5,40.25 17.2,39.94 17.1,39.94 17.05,39.89 15.04,39.89 15.03,39.88 14.82,39.88 13.87,38.94 13.29,38.94 13.14,39.08 13.14,40.5 13.64,40.99 15.4,40.99 16.16,41.75 16.16,43.13 15.32,43.96 15.32,44.69 15.63,45 19.69,45 20.83,46.14 21.87,46.14
USBPWR1 on IN1 (solid shape): 22,45.97 22,43.56 18.55,40.11 17.26,40.11 16.92,39.77 14.94,39.77 13.82,38.65 13.51,38.65 13.09,39.07 13.09,40.35 13.44,40.71 14.99,40.71 16.06,41.78 16.06,43.15 15.37,43.83 15.37,44.8 15.55,44.98 17.3,44.98 17.63,45.31 19.71,45.31 20.63,46.22 21.74,46.22
V_BLIGHT on BOTTOM (solid shape): 112.63,171.29 112.63,170.88 112.92,170.59 112.92,168.81 112.92,168.81 112.92,167.56 112.3,166.93 112.3,165.73 112.04,165.47 110.19,165.47 110.06,165.6 110.06,166.31 110.98,167.23 110.98,170.05 110.44,170.58 110.44,171.2 111.61,171.2 111.61,171.46 110.44,171.46 110.44,171.7 112.21,171.7
VA1 on TOP (solid shape): outline of 90 points within 182.27,164.31 195.07,183.05
VA1 on BOTTOM (solid shape): 192.82,172.79 192.82,171.87 192.54,171.6 188.95,171.6 188.7,171.85 188.7,173.58 188.95,173.83 191.77,173.83
VA1 on IN1 (solid shape): 192.92,173.09 192.92,171.93 192.55,171.56 189.09,171.56 188.82,171.84 188.82,173.61 188.98,173.78 192.23,173.78
VA1 on IN2 (solid shape): 192.99,172.92 192.99,172.2 192.71,171.93 190.72,171.93 190.7,171.94 189.04,171.94 188.68,172.31 188.68,173.32 189.26,173.91 192,173.91
VA2 on TOP (solid shape): 190.81,187.6 190.81,185.72 191.16,185.36 192.36,185.36 192.43,185.29 192.43,182.34 192.18,182.09 191.47,182.09 190.23,183.33 185.21,183.33 185.04,183.5 185.04,187.75 185.32,188.03 190.38,188.03
VREFC_VMA1 on IN2 (solid shape): outline of 376 points within 116.36,160.85 125.86,163.9
VREFD_VMA1 on TOP (solid shape): 116.03,169.59 116.03,169.06 115.79,168.81 114.8,168.81 114.68,168.7 114.68,167.94 114.61,167.86 114.12,167.86 114.02,167.96 114.02,168.7 113.9,168.83 112.42,168.83 112.37,168.88 112.37,169.66 112.47,169.77 115.85,169.77
N35990640 on TOP (solid shape): 108.41,168.98 108.41,168.4 106.95,166.94 104.25,166.94 104.2,166.99 104.2,168.23 105.74,168.23 106.48,168.96 107.16,168.96 107.37,169.18 108.22,169.18
N35990640 on BOTTOM (solid shape): 111.61,174.19 111.61,173.96 110.44,173.96 110.44,173.71 111.61,173.71 111.61,173.46 110.43,173.46 110.43,173.21 111.61,173.21 111.61,172.97 111.6,172.96 110.26,172.96 109.41,172.11 108.79,172.11 107.22,170.54 107.22,169.95 107.09,169.66 107.22,169.38 107.22,167.72 106.7,167.19 105.8,167.19 105.68,167.32 105.68,170.6 109.27,174.19 109.3,174.21 111.58,174.21
N36013518 on TOP (solid shape): 16.72,69.74 16.72,68.85 15.35,67.48 14.05,67.48 12.63,66.06 5.59,66.06 4.96,66.69 4.96,67.84 5.07,67.95 5.4,67.95 5.41,67.96 9.58,67.96 9.62,67.93 11.37,67.93 12.81,69.36 13.97,69.36 14.52,69.91 16.55,69.91
N36013609 on BOTTOM (solid shape): 25.35,94.79 25.35,92.91 26.75,91.51 26.75,89.93 25.71,88.89 25.71,86.89 25.49,86.67 23.92,86.67 23.58,87.01 23.58,88.77 24.64,89.83 24.64,91.03 22.31,93.36 22.31,94.76 22.48,94.94 25.2,94.94
N36013670 on BOTTOM (solid shape): 28.72,75.24 28.83,75.23 28.95,75.25 28.98,75.25 29.07,75.15 30.08,75.15 30.46,74.77 30.46,74.54 29.95,74.03 29.95,73.42 29.72,73.2 27.15,73.2 27,73.35 27,73.95 28.33,73.95 28.33,74.47 27,74.47 27,75.18 27.07,75.25 28.71,75.25
N36013670 on IN2 (solid shape): 30.54,81.9 30.54,75.06 29.87,74.39 28.9,74.39 28.75,74.54 28.75,75.11 28.77,75.18 28.84,75.21 29.2,75.47 29.1,75.89 29.08,75.96 29.1,76.02 29.19,76.36 28.98,76.64 28.92,76.73 28.98,76.82 29.17,77.01 29.18,77.28 29.19,77.36 29.26,77.41 29.55,77.77 29.3,78.16 29.24,78.22 29.24,78.3 29.2,78.68 28.86,78.85 28.78,78.87 28.75,78.95 28.75,79.23 28.78,79.3 28.85,79.33 29.23,79.56 29.16,80 29.13,80.08 29.17,80.16 29.32,80.64 28.87,80.87 28.79,80.89 28.75,80.97 28.75,81.86 29.03,82.14 30.31,82.14
N36013751 on TOP (solid shape): 11.23,84.53 9.88,83.19 4.84,83.19 4.84,83.95 5.67,84.78 9.12,84.78 9.87,85.53 9.87,86.19 10.14,86.45 11.23,86.45
N36042480 on TOP (solid shape): 198.02,185.29 198.02,180.41 197.64,180.03 194.06,180.03 193.83,180.26 193.83,180.69 192.89,181.63 192.89,184.82 193.45,185.37 197.93,185.37
N36042544 on BOTTOM (solid shape): 174.15,187.39 175.49,187.39 175.57,187.32 175.57,184.12 174.4,182.95 174.4,181.22 174.2,181.02 172.42,181.02 172.11,180.71 171.73,180.71 171.53,180.92 171.53,181.35 171.71,181.53 171.71,183.18 172.24,183.18 172.24,183.12 172.26,183.06 172.28,183.01 172.3,182.95 172.34,182.9 172.38,182.86 172.42,182.82 172.47,182.79 172.53,182.77 172.59,182.75 172.64,182.75 172.7,182.75 172.76,182.75 172.82,182.77 172.87,182.79 172.92,182.82 172.97,182.86 173.01,182.9 173.04,182.95 173.07,183.01 173.09,183.06 173.1,183.12 173.11,183.18 173.1,183.24 173.09,183.29 173.07,183.35 173.04,183.4 173.01,183.45 172.97,183.49 172.92,183.53 172.87,183.56 172.82,183.59 172.76,183.6 172.7,183.61 172.64,183.61 172.59,183.6 172.53,183.59 172.47,183.56 172.42,183.53 172.38,183.49 172.34,183.45 172.3,183.4 172.28,183.35 172.26,183.29 172.24,183.24 172.24,183.18 171.71,183.18 171.71,187.57 171.96,187.83 173.71,187.83
N36042603 on TOP (solid shape): 191.32,181.73 191.32,181.12 191.27,181.07 189.26,181.07 189.12,181.21 189.12,182.27 189.24,182.39 190.66,182.39
N36042603 on TOP (solid shape): 184.46,185.84 184.46,183.56 184.21,183.3 182.48,183.3 182.25,183.53 182.25,185.82 182.45,186.02 184.28,186.02
N36042641 on TOP (solid shape): 183.11,188.46 183.11,188.18 182.96,188.03 180.88,188.03 180.57,187.72 180.57,186.56 180.34,186.33 179.33,186.33 179.23,186.43 179.23,187.78 180.06,188.61 182.96,188.61
N36062147 on BOTTOM (solid shape): 161.68,137.46 161.88,137.46 161.88,138.45 162.18,138.45 162.18,137.46 162.39,137.46 162.39,138.45 162.66,138.45 162.69,138.42 162.69,136.26 165.24,133.71 165.24,129.87 164.88,129.51 161.35,129.51 161,129.85 161,138.13 161.32,138.45 161.68,138.45
N36062279 on TOP (solid shape): 53.52,107.69 53.52,105.86 53.29,105.63 52.33,105.63 52.2,105.76 52.2,106.42 51.95,106.67 51.26,106.67 49.89,108.04 48.04,108.04 47.78,108.3 47.78,109.19 47.9,109.3 49.48,109.3 51.91,109.3
N36062324 on TOP (solid shape): 47.3,110.13 47.3,108.43 48.01,107.71 48.39,107.71 48.49,107.61 48.49,106.52 48.42,106.44 46.97,106.44 45.75,107.67 45.75,109.37 45.34,109.77 45.34,110.79 45.52,110.97 46.46,110.97
N36062358 on TOP (solid shape): 55.99,108.68 56.57,108.68 57.08,108.17 57.08,106.44 57.04,106.41 57.03,106.41 56.86,106.31 56.76,106.14 56.76,106.12 56.72,106.09 55.35,106.09 54.82,105.56 54.06,105.56 53.8,105.81 53.8,108.25 53.26,108.79 53.26,109.23 53.33,109.3 54.94,109.3 54.94,109.31 54.97,109.34 55.33,109.34
N38261008 on TOP (solid shape): 20.4,110.39 20.4,109.78 20.63,109.55 22.14,109.55 22.42,109.27 22.42,108.41 21.7,107.69 20.17,107.69 19.16,108.71 19.16,110.08 19.16,110.41 19.28,110.53 20.26,110.53

Small or netless copper shapes (teardrops, artwork), in the pictures only: 114 on TOP, 16 on BOTTOM, 94 on IN1, 8 on IN2

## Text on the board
Ref Des/Silkscreen Bottom: MODEL:Z8B | REV:C | DA0Z8BMB6C0
User.Comments: 202.63 | 196.03 | 39.0x106.0 | PARTITION_3 | PARTITION_2 | PARTITION_4
Ref Des/Silkscreen Top: DA0Z8BMB6C0 | REV:C
BODY_CENTER: 202,63 | 196,03
User.10: GND | ADOGND | VIN | +VCCIN | +5V_S5 | +3VPCU | +5V | +1.05V | +VGPU_CORE | +3V_S5
User.12: GND | ADOGND
User.23: REV:A-10
User.26: 202,63 | 196,03
User.45: XY-Check acute:May 10 19:28:15 2014 | XY-Check cline width:May 10 18:35:50 2014 | XY-Check rotation:Nov 04 11:36:31 2013 | XY-Check txt overlap:Nov 04 11:35:50 2013 | XY-Check txt:Nov 04 11:36:37 2013 | XY-Create nettxt:Oct 29 20:13:29 2013 | XY-Create plane:May 07 20:55:33 2014 | XY-Cross plane-BOTTOM-SGND:May 10 19:30:16 2014 | XY-Cross plane-IN1-SVCC:May 10 19:30:03 2014 | XY-Cross plane-IN2-SGND:May 10 19:30:11 2014 | XY-Cross plane-TOP-SVCC:May 10 19:29:44 2014 | XY-Dxf to pin check:May 10 19:24:54 2014 | XY-Etch cross-IN1-IN2:May 10 19:29:57 2014 | XY-Etch ref-BOTTOM-SGND:May 10 19:30:22 2014 | XY-Etch ref-IN1-SVCC:May 10 19:30:11 2014 | XY-Etch ref-IN2-SGND:May 10 19:30:16 2014 | XY-Etch ref-TOP-SVCC:May 10 19:29:57 2014 | XY-Mask check:May 10 18:38:37 2014 | XY-Norefdes:Nov 04 11:36:22 2013 | XY-Outline check:May 10 19:31:17 2014 | XY-Plane net check:May 10 19:25:39 2014 | XY-Prop check:May 10 19:29:41 2014 | XY-Symbol cross:May 10 19:26:52 2014 | XY-Via check:May 10 19:30:36 2014 | check acute:May 09 14:08:42 2014 | check rotation:Nov 02 22:01:17 2013 | check txt overlap:Nov 02 22:14:47 2013 | create nettxt:May 08 19:36:49 2014 | create plane:May 09 17:10:54 2014 | cross plane-BOTTOM-SGND:Nov 01 00:32:53 2013 | cross plane-IN1-SVCC:Nov 01 00:32:43 2013 | cross plane-IN2-SGND:Nov 01 00:32:49 2013 | cross plane-TOP-SVCC:Nov 01 00:32:35 2013 | etch cross-IN1-IN2:Nov 01 00:32:40 2013 | etch ref-BOTTOM-SGND:Nov 01 00:32:59 2013 | etch ref-IN1-SVCC:Nov 01 00:32:49 2013 | etch ref-IN2-SGND:Nov 01 00:32:53 2013 | etch ref-TOP-SVCC:Nov 01 00:32:40 2013 | prop check:Nov 01 00:32:23 2013 | via check:Nov 01 00:34:08 2013 | FIGURE | TYPE | Circle | Oblong | SIZE | 10.0 | 12.0 | 14.0 | 22.0 | 24.0 | 28.0 | 31.0 | 35.0 | 39.0 | 118.0 | 140.0 | 158.0 | 189.0 | 37.0 | 43.0 | 47.0 | 51.0 | 63.0 | 71.0 | 102.0 | 177.0 | 300.0 | 55.0x28.0 | 59.0x24.0 | 63.0x35.0 | 67.0x24.0 | 91.0x35.0 | 94.0x28.0 | 94.0x39.0 | 98.0x24.0 | DRILL CHART: TOP to BOTTOM | ALL UNITS ARE IN MILS | PLATED | NON-PLATED | ROTATION | - | 0.000 | 90.000 | QTY | 4680 | 38 | 680 | 19 | 70 | 22 | 31 | 12 | 8 | 11 | 3 | 1 | 2 | 6 | 5598 | 7 | 4 | 25 | TOTAL HOLES:
